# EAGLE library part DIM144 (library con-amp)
AMP connector
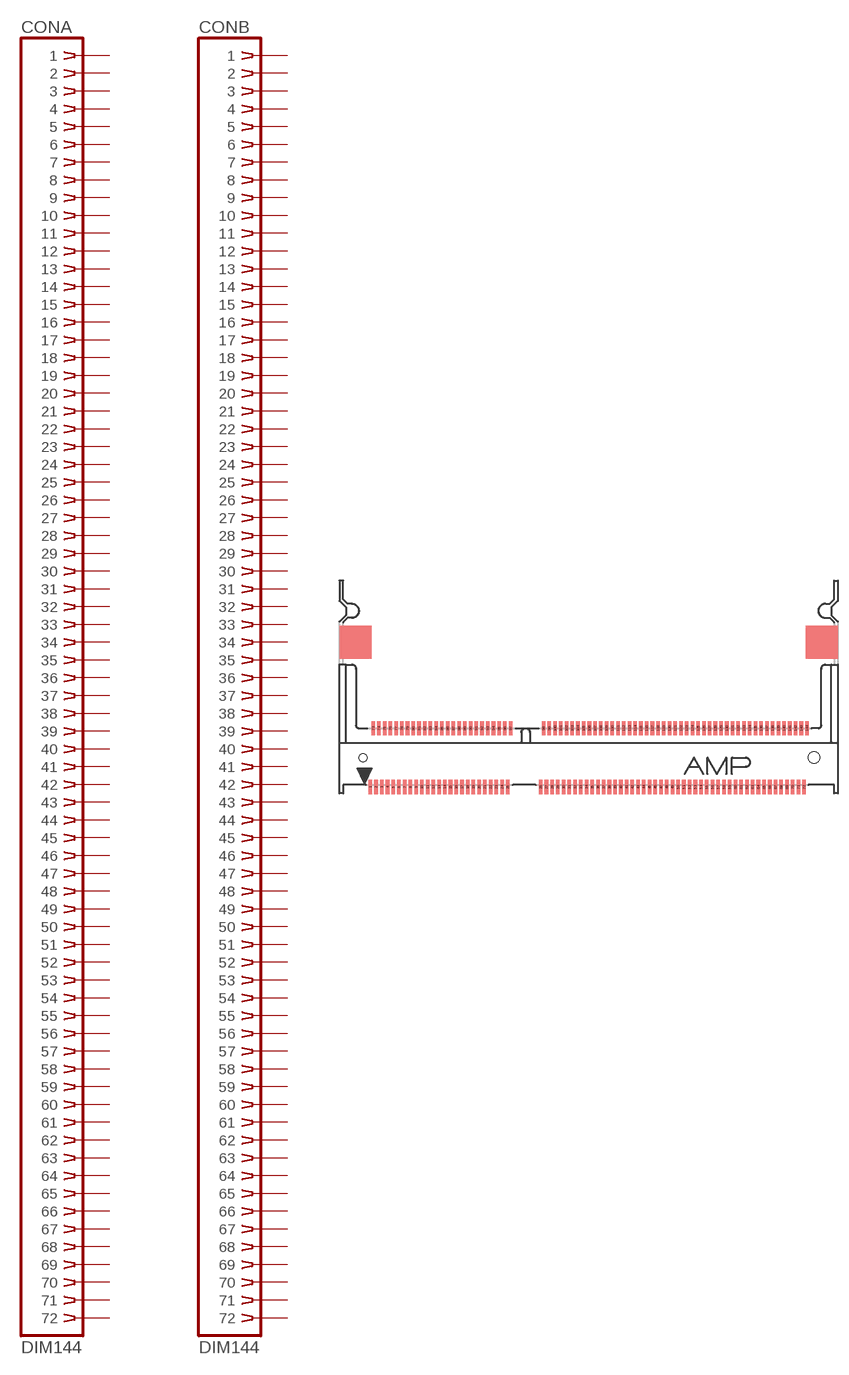
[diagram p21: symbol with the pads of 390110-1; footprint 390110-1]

Designator prefix CON; gates A=SIMM72 B=SIMM72

## DIM144 (MF: TYCO ELECTRONICS; MPN: 390110-1; OC_FARNELL: 1095867; OC_NEWARK: 33B8449)  [390110-1]
1  A:1  pas
2  A:2  pas
3  A:3  pas
4  A:4  pas
5  A:5  pas
6  A:6  pas
7  A:7  pas
8  A:8  pas
9  A:9  pas
10  A:10  pas
11  A:11  pas
12  A:12  pas
13  A:13  pas
14  A:14  pas
15  A:15  pas
16  A:16  pas
17  A:17  pas
18  A:18  pas
19  A:19  pas
20  A:20  pas
21  A:21  pas
22  A:22  pas
23  A:23  pas
24  A:24  pas
25  A:25  pas
26  A:26  pas
27  A:27  pas
28  A:28  pas
29  A:29  pas
30  A:30  pas
31  A:31  pas
32  A:32  pas
33  A:33  pas
34  A:34  pas
35  A:35  pas
36  A:36  pas
37  A:37  pas
38  A:38  pas
39  A:39  pas
40  A:40  pas
41  A:41  pas
42  A:42  pas
43  A:43  pas
44  A:44  pas
45  A:45  pas
46  A:46  pas
47  A:47  pas
48  A:48  pas
49  A:49  pas
50  A:50  pas
51  A:51  pas
52  A:52  pas
53  A:53  pas
54  A:54  pas
55  A:55  pas
56  A:56  pas
57  A:57  pas
58  A:58  pas
59  A:59  pas
60  A:60  pas
61  A:61  pas
62  A:62  pas
63  A:63  pas
64  A:64  pas
65  A:65  pas
66  A:66  pas
67  A:67  pas
68  A:68  pas
69  A:69  pas
70  A:70  pas
71  A:71  pas
72  A:72  pas
73  B:1  pas
74  B:2  pas
75  B:3  pas
76  B:4  pas
77  B:5  pas
78  B:6  pas
79  B:7  pas
80  B:8  pas
81  B:9  pas
82  B:10  pas
83  B:11  pas
84  B:12  pas
85  B:13  pas
86  B:14  pas
87  B:15  pas
88  B:16  pas
89  B:17  pas
90  B:18  pas
91  B:19  pas
92  B:20  pas
93  B:21  pas
94  B:22  pas
95  B:23  pas
96  B:24  pas
97  B:25  pas
98  B:26  pas
99  B:27  pas
100  B:28  pas
101  B:29  pas
102  B:30  pas
103  B:31  pas
104  B:32  pas
105  B:33  pas
106  B:34  pas
107  B:35  pas
108  B:36  pas
109  B:37  pas
110  B:38  pas
111  B:39  pas
112  B:40  pas
113  B:41  pas
114  B:42  pas
115  B:43  pas
116  B:44  pas
117  B:45  pas
118  B:46  pas
119  B:47  pas
120  B:48  pas
121  B:49  pas
122  B:50  pas
123  B:51  pas
124  B:52  pas
125  B:53  pas
126  B:54  pas
127  B:55  pas
128  B:56  pas
129  B:57  pas
130  B:58  pas
131  B:59  pas
132  B:60  pas
133  B:61  pas
134  B:62  pas
135  B:63  pas
136  B:64  pas
137  B:65  pas
138  B:66  pas
139  B:67  pas
140  B:68  pas
141  B:69  pas
142  B:70  pas
143  B:71  pas
144  B:72  pas

## Footprint 390110-1 (pad centres in mm)
SO DIMM Socket Dual Read-Out SGRAM Memory Modules
smd 0.5 x 2: 1 -30.5,-4.1; 2 -29.7,-4.1; 3 -28.9,-4.1; 4 -28.1,-4.1; 5 -27.3,-4.1; 6 -26.5,-4.1; 7 -25.7,-4.1; 8 -24.9,-4.1; 9 -24.1,-4.1; 10 -23.3,-4.1; 11 -22.5,-4.1; 12 -21.7,-4.1; 13 -20.9,-4.1; 14 -20.1,-4.1; 15 -19.3,-4.1; 16 -18.5,-4.1; 17 -17.7,-4.1; 18 -16.9,-4.1; 19 -16.1,-4.1; 20 -15.3,-4.1; 21 -14.5,-4.1; 22 -13.7,-4.1; 23 -12.9,-4.1; 24 -12.1,-4.1; 25 -11.3,-4.1; 26 -6.7,-4.1; 27 -5.9,-4.1; 28 -5.1,-4.1; 29 -4.3,-4.1; 30 -3.5,-4.1; 31 -2.7,-4.1; 32 -1.9,-4.1; 33 -1.1,-4.1; 34 -0.3,-4.1; 35 0.5,-4.1; 36 1.3,-4.1; 37 2.1,-4.1; 38 2.9,-4.1; 39 3.7,-4.1; 40 4.5,-4.1; 41 5.3,-4.1; 42 6.1,-4.1; 43 6.9,-4.1; 44 7.7,-4.1; 45 8.5,-4.1; 46 9.3,-4.1; 47 10.1,-4.1; 48 10.9,-4.1; 49 11.7,-4.1; 50 12.5,-4.1; 51 13.3,-4.1; 52 14.1,-4.1; 53 14.9,-4.1; 54 15.7,-4.1; 55 16.5,-4.1; 56 17.3,-4.1; 57 18.1,-4.1; 58 18.9,-4.1; 59 19.7,-4.1; 60 20.5,-4.1; 61 21.3,-4.1; 62 22.1,-4.1; 63 22.9,-4.1; 64 23.7,-4.1; 65 24.5,-4.1; 66 25.3,-4.1; 67 26.1,-4.1; 68 26.9,-4.1; 69 27.7,-4.1; 70 28.5,-4.1; 71 29.3,-4.1; 72 30.1,-4.1; 73 -30.1,4.1; 74 -29.3,4.1; 75 -28.5,4.1; 76 -27.7,4.1; 77 -26.9,4.1; 78 -26.1,4.1; 79 -25.3,4.1; 80 -24.5,4.1; 81 -23.7,4.1; 82 -22.9,4.1; 83 -22.1,4.1; 84 -21.3,4.1; 85 -20.5,4.1; 86 -19.7,4.1; 87 -18.9,4.1; 88 -18.1,4.1; 89 -17.3,4.1; 90 -16.5,4.1; 91 -15.7,4.1; 92 -14.9,4.1; 93 -14.1,4.1; 94 -13.3,4.1; 95 -12.5,4.1; 96 -11.7,4.1; 97 -10.9,4.1; 98 -6.3,4.1; 99 -5.5,4.1; 100 -4.7,4.1; 101 -3.9,4.1; 102 -3.1,4.1; 103 -2.3,4.1; 104 -1.5,4.1; 105 -0.7,4.1; 106 0.1,4.1; 107 0.9,4.1; 108 1.7,4.1; 109 2.5,4.1; 110 3.3,4.1; 111 4.1,4.1; 112 4.9,4.1; 113 5.7,4.1; 114 6.5,4.1; 115 7.3,4.1; 116 8.1,4.1; 117 8.9,4.1; 118 9.7,4.1; 119 10.5,4.1; 120 11.3,4.1; 121 12.1,4.1; 122 12.9,4.1; 123 13.7,4.1; 124 14.5,4.1; 125 15.3,4.1; 126 16.1,4.1; 127 16.9,4.1; 128 17.7,4.1; 129 18.5,4.1; 130 19.3,4.1; 131 20.1,4.1; 132 20.9,4.1; 133 21.7,4.1; 134 22.5,4.1; 135 23.3,4.1; 136 24.1,4.1; 137 24.9,4.1; 138 25.7,4.1; 139 26.5,4.1; 140 27.3,4.1; 141 28.1,4.1; 142 28.9,4.1; 143 29.7,4.1; 144 30.5,4.1
hole 1.1 at -31.5,0
hole 1.6 at 31.5,0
